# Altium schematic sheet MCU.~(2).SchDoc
size A3; SheetNumber: 1; SheetTotal: 2
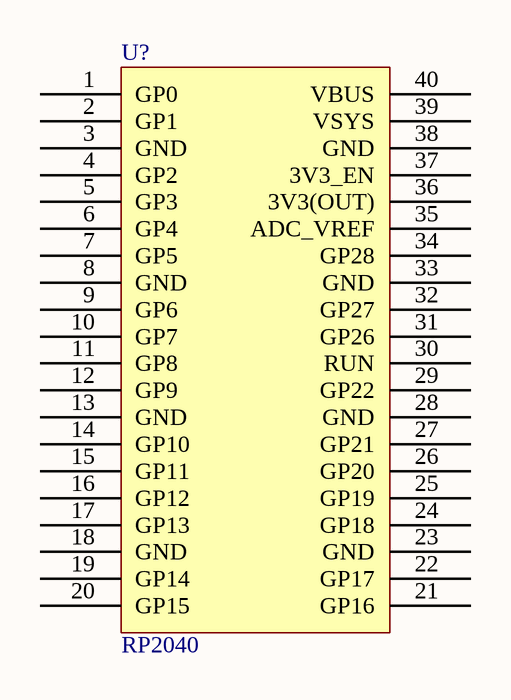
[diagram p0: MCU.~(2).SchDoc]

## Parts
U?  RP2040

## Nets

Not connected (* = marked no-connect by the designer): U? 1(GP0) 2(GP1) 3(GND) 4(GP2) 5(GP3) 6(GP4) 7(GP5) 8(GND) 9(GP6) 10(GP7) 11(GP8) 12(GP9) 13(GND) 14(GP10) 15(GP11) 16(GP12) 17(GP13) 18(GND) 19(GP14) 20(GP15) 21(GP16) 22(GP17) 23(GND) 24(GP18) 25(GP19) 26(GP20) 27(GP21) 28(GND) 29(GP22) 30(RUN) 31(GP26) 32(GP27) 33(GND) 34(GP28) 35(ADC_VREF) 36(3V3(OUT)) 37(3V3_EN) 38(GND) 39(VSYS) 40(VBUS)

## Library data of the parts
U? = Component_1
